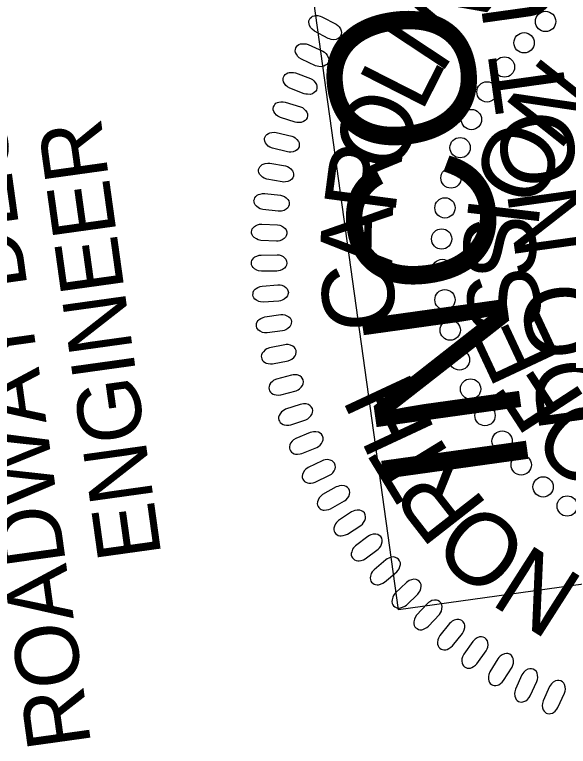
# Model space of a CAD drawing. Extents: x 477288 to 478604, y 497629 to 499448.
# Drawn here: x 477375.5 to 477419.1, y 499110 to 499167.6 of the extents above; entities that cross this region are included whole.
import ezdxf

# ---------------------------------------------------------------- set-up
doc = ezdxf.new("R2010")
doc.units = 0
for name, color, linetype in [('Sheet PE Seal Cell', 7, 'Continuous'), ('Sheet Plan CELL', 7, 'Continuous'), ('Sheet Sticker Incomplete CELL', 7, 'Continuous')]:
    doc.layers.add(name, color=color, linetype=linetype)

msp = doc.modelspace()

# ---------------------------------------------------------------- linework, layer by layer
at = {"layer": 'Sheet PE Seal Cell'}
for points in [[(477400.198, 499165.737), (477399.116, 499166.315), (477398.94, 499166.451), (477398.841, 499166.563), (477398.745, 499166.742), (477398.694, 499166.879), (477398.676, 499167.015), (477398.69, 499167.127), (477398.725, 499167.236), (477398.796, 499167.325), (477398.878, 499167.416), (477398.98, 499167.48), (477399.118, 499167.526), (477399.217, 499167.541), (477399.38, 499167.53), (477399.566, 499167.498), (477399.718, 499167.443), (477400.83, 499166.857), (477400.969, 499166.757), (477401.071, 499166.652), (477401.17, 499166.498), (477401.24, 499166.333), (477401.264, 499166.21), (477401.243, 499166.044), (477401.19, 499165.902), (477401.085, 499165.789), (477400.992, 499165.72), (477400.844, 499165.655), (477400.638, 499165.63), (477400.448, 499165.655), (477400.319, 499165.689)], [(477399.213, 499163.581), (477398.097, 499164.09), (477397.912, 499164.215), (477397.807, 499164.32), (477397.699, 499164.492), (477397.639, 499164.626), (477397.613, 499164.762), (477397.621, 499164.873), (477397.649, 499164.984), (477397.714, 499165.077), (477397.791, 499165.173), (477397.888, 499165.244), (477398.023, 499165.298), (477398.12, 499165.319), (477398.284, 499165.319), (477398.472, 499165.299), (477398.627, 499165.253), (477399.773, 499164.739), (477399.918, 499164.648), (477400.026, 499164.549), (477400.134, 499164.401), (477400.215, 499164.242), (477400.248, 499164.12), (477400.237, 499163.952), (477400.193, 499163.808), (477400.095, 499163.689), (477400.006, 499163.614), (477399.863, 499163.539), (477399.659, 499163.501), (477399.467, 499163.514), (477399.337, 499163.541)], [(477398.323, 499161.379), (477397.177, 499161.817), (477396.986, 499161.93), (477396.873, 499162.028), (477396.755, 499162.194), (477396.687, 499162.324), (477396.653, 499162.457), (477396.653, 499162.569), (477396.674, 499162.681), (477396.733, 499162.778), (477396.804, 499162.879), (477396.896, 499162.956), (477397.027, 499163.018), (477397.123, 499163.045), (477397.286, 499163.055), (477397.476, 499163.047), (477397.633, 499163.011), (477398.809, 499162.57), (477398.96, 499162.488), (477399.074, 499162.397), (477399.191, 499162.256), (477399.282, 499162.101), (477399.322, 499161.982), (477399.322, 499161.814), (477399.287, 499161.667), (477399.197, 499161.542), (477399.112, 499161.462), (477398.974, 499161.379), (477398.773, 499161.327), (477398.581, 499161.329), (477398.449, 499161.347)], [(477397.61, 499159.136), (477396.439, 499159.5), (477396.241, 499159.601), (477396.123, 499159.693), (477395.994, 499159.85), (477395.918, 499159.975), (477395.876, 499160.106), (477395.868, 499160.218), (477395.883, 499160.331), (477395.936, 499160.432), (477395.999, 499160.538), (477396.087, 499160.62), (477396.214, 499160.69), (477396.308, 499160.723), (477396.471, 499160.743), (477396.66, 499160.747), (477396.819, 499160.721), (477398.021, 499160.354), (477398.176, 499160.283), (477398.296, 499160.198), (477398.422, 499160.065), (477398.522, 499159.916), (477398.569, 499159.8), (477398.58, 499159.632), (477398.554, 499159.483), (477398.472, 499159.353), (477398.393, 499159.268), (477398.26, 499159.176), (477398.063, 499159.112), (477397.871, 499159.101), (477397.739, 499159.112)], [(477396.994, 499156.787), (477395.802, 499157.077), (477395.598, 499157.166), (477395.474, 499157.249), (477395.336, 499157.399), (477395.253, 499157.519), (477395.202, 499157.647), (477395.188, 499157.758), (477395.194, 499157.872), (477395.241, 499157.975), (477395.298, 499158.085), (477395.381, 499158.172), (477395.503, 499158.251), (477395.594, 499158.29), (477395.755, 499158.32), (477395.944, 499158.336), (477396.105, 499158.32), (477397.327, 499158.029), (477397.487, 499157.967), (477397.612, 499157.89), (477397.745, 499157.766), (477397.855, 499157.624), (477397.909, 499157.511), (477397.93, 499157.343), (477397.914, 499157.194), (477397.84, 499157.058), (477397.767, 499156.968), (477397.64, 499156.868), (477397.446, 499156.793), (477397.256, 499156.769), (477397.123, 499156.771)], [(477396.581, 499154.424), (477395.373, 499154.639), (477395.163, 499154.715), (477395.035, 499154.791), (477394.888, 499154.931), (477394.797, 499155.046), (477394.738, 499155.17), (477394.717, 499155.28), (477394.717, 499155.394), (477394.756, 499155.501), (477394.807, 499155.613), (477394.884, 499155.706), (477395.001, 499155.791), (477395.09, 499155.836), (477395.249, 499155.876), (477395.436, 499155.904), (477395.597, 499155.898), (477396.835, 499155.685), (477396.999, 499155.633), (477397.128, 499155.564), (477397.27, 499155.448), (477397.387, 499155.313), (477397.449, 499155.204), (477397.48, 499155.038), (477397.473, 499154.887), (477397.408, 499154.748), (477397.341, 499154.654), (477397.22, 499154.546), (477397.033, 499154.458), (477396.844, 499154.423), (477396.711, 499154.416)], [(477396.275, 499152.11), (477395.056, 499152.248), (477394.843, 499152.31), (477394.709, 499152.379), (477394.553, 499152.509), (477394.455, 499152.618), (477394.389, 499152.738), (477394.361, 499152.847), (477394.354, 499152.961), (477394.386, 499153.07), (477394.43, 499153.185), (477394.501, 499153.282), (477394.612, 499153.375), (477394.698, 499153.425), (477394.854, 499153.475), (477395.039, 499153.515), (477395.201, 499153.519), (477396.45, 499153.384), (477396.616, 499153.342), (477396.749, 499153.282), (477396.898, 499153.175), (477397.024, 499153.047), (477397.092, 499152.942), (477397.134, 499152.779), (477397.137, 499152.629), (477397.08, 499152.485), (477397.019, 499152.386), (477396.905, 499152.271), (477396.723, 499152.171), (477396.537, 499152.125), (477396.406, 499152.11)], [(477396.123, 499149.761), (477394.898, 499149.823), (477394.681, 499149.872), (477394.544, 499149.931), (477394.381, 499150.052), (477394.276, 499150.154), (477394.202, 499150.27), (477394.167, 499150.377), (477394.153, 499150.49), (477394.178, 499150.601), (477394.215, 499150.719), (477394.28, 499150.82), (477394.385, 499150.92), (477394.467, 499150.975), (477394.62, 499151.035), (477394.802, 499151.086), (477394.963, 499151.1), (477396.218, 499151.044), (477396.386, 499151.013), (477396.523, 499150.961), (477396.678, 499150.863), (477396.812, 499150.744), (477396.887, 499150.643), (477396.939, 499150.484), (477396.951, 499150.333), (477396.904, 499150.186), (477396.849, 499150.084), (477396.743, 499149.962), (477396.567, 499149.851), (477396.385, 499149.793), (477396.253, 499149.77)], [(477396.162, 499147.405), (477394.935, 499147.39), (477394.715, 499147.424), (477394.575, 499147.475), (477394.404, 499147.585), (477394.293, 499147.681), (477394.212, 499147.792), (477394.171, 499147.896), (477394.15, 499148.008), (477394.169, 499148.121), (477394.197, 499148.24), (477394.255, 499148.346), (477394.354, 499148.451), (477394.433, 499148.512), (477394.582, 499148.582), (477394.761, 499148.643), (477394.919, 499148.668), (477396.176, 499148.691), (477396.346, 499148.67), (477396.486, 499148.627), (477396.647, 499148.54), (477396.787, 499148.429), (477396.868, 499148.333), (477396.93, 499148.177), (477396.952, 499148.028), (477396.914, 499147.878), (477396.866, 499147.772), (477396.768, 499147.644), (477396.599, 499147.522), (477396.42, 499147.453), (477396.291, 499147.421)], [(477396.314, 499145.041), (477395.091, 499144.949), (477394.869, 499144.969), (477394.726, 499145.011), (477394.548, 499145.11), (477394.432, 499145.199), (477394.344, 499145.305), (477394.297, 499145.406), (477394.268, 499145.517), (477394.28, 499145.63), (477394.3, 499145.751), (477394.352, 499145.86), (477394.443, 499145.972), (477394.519, 499146.037), (477394.663, 499146.116), (477394.837, 499146.189), (477394.994, 499146.224), (477396.248, 499146.325), (477396.418, 499146.316), (477396.561, 499146.281), (477396.726, 499146.204), (477396.874, 499146.103), (477396.961, 499146.012), (477397.033, 499145.859), (477397.064, 499145.712), (477397.035, 499145.56), (477396.993, 499145.452), (477396.903, 499145.317), (477396.743, 499145.186), (477396.569, 499145.105), (477396.442, 499145.066)], [(477396.613, 499142.7), (477395.398, 499142.532), (477395.176, 499142.539), (477395.029, 499142.572), (477394.847, 499142.659), (477394.724, 499142.74), (477394.63, 499142.84), (477394.576, 499142.938), (477394.541, 499143.047), (477394.545, 499143.161), (477394.558, 499143.283), (477394.603, 499143.395), (477394.688, 499143.512), (477394.759, 499143.583), (477394.898, 499143.67), (477395.067, 499143.754), (477395.222, 499143.798), (477396.466, 499143.978), (477396.637, 499143.98), (477396.781, 499143.954), (477396.951, 499143.887), (477397.106, 499143.795), (477397.198, 499143.71), (477397.279, 499143.562), (477397.319, 499143.418), (477397.3, 499143.264), (477397.265, 499143.154), (477397.184, 499143.013), (477397.032, 499142.872), (477396.864, 499142.781), (477396.739, 499142.733)], [(477396.776, 499141.597), (477395.573, 499141.352), (477395.366, 499141.272), (477395.24, 499141.193), (477395.096, 499141.049), (477395.008, 499140.932), (477394.952, 499140.806), (477394.934, 499140.696), (477394.937, 499140.582), (477394.979, 499140.476), (477395.032, 499140.365), (477395.111, 499140.274), (477395.23, 499140.192), (477395.32, 499140.149), (477395.48, 499140.113), (477395.668, 499140.09), (477395.828, 499140.1), (477397.061, 499140.343), (477397.223, 499140.399), (477397.351, 499140.471), (477397.489, 499140.59), (477397.604, 499140.729), (477397.663, 499140.839), (477397.69, 499141.005), (477397.68, 499141.156), (477397.611, 499141.294), (477397.541, 499141.387), (477397.418, 499141.491), (477397.228, 499141.575), (477397.038, 499141.605), (477396.905, 499141.609)], [(477397.312, 499139.21), (477396.128, 499138.89), (477395.926, 499138.797), (477395.805, 499138.71), (477395.67, 499138.558), (477395.59, 499138.435), (477395.542, 499138.307), (477395.531, 499138.195), (477395.541, 499138.081), (477395.589, 499137.978), (477395.649, 499137.871), (477395.734, 499137.785), (477395.858, 499137.71), (477395.95, 499137.673), (477396.112, 499137.647), (477396.301, 499137.636), (477396.461, 499137.656), (477397.676, 499137.977), (477397.834, 499138.042), (477397.957, 499138.122), (477398.088, 499138.25), (477398.193, 499138.395), (477398.245, 499138.509), (477398.262, 499138.677), (477398.243, 499138.826), (477398.165, 499138.96), (477398.089, 499139.048), (477397.96, 499139.145), (477397.766, 499139.216), (477397.575, 499139.234), (477397.442, 499139.229)], [(477398.005, 499136.902), (477396.844, 499136.509), (477396.648, 499136.403), (477396.532, 499136.309), (477396.407, 499136.148), (477396.335, 499136.021), (477396.295, 499135.89), (477396.291, 499135.778), (477396.308, 499135.665), (477396.363, 499135.565), (477396.429, 499135.462), (477396.519, 499135.381), (477396.648, 499135.314), (477396.743, 499135.283), (477396.906, 499135.268), (477397.095, 499135.268), (477397.253, 499135.298), (477398.446, 499135.694), (477398.599, 499135.77), (477398.717, 499135.857), (477398.84, 499135.993), (477398.936, 499136.144), (477398.98, 499136.262), (477398.986, 499136.43), (477398.957, 499136.577), (477398.872, 499136.707), (477398.791, 499136.79), (477398.656, 499136.878), (477398.457, 499136.937), (477398.265, 499136.943), (477398.133, 499136.929)], [(477398.791, 499134.684), (477397.656, 499134.219), (477397.467, 499134.101), (477397.357, 499133.999), (477397.243, 499133.831), (477397.179, 499133.7), (477397.147, 499133.566), (477397.15, 499133.453), (477397.174, 499133.342), (477397.235, 499133.246), (477397.308, 499133.147), (477397.403, 499133.073), (477397.535, 499133.014), (477397.632, 499132.989), (477397.796, 499132.983), (477397.984, 499132.996), (477398.141, 499133.036), (477399.306, 499133.506), (477399.454, 499133.591), (477399.566, 499133.686), (477399.68, 499133.829), (477399.767, 499133.986), (477399.803, 499134.106), (477399.8, 499134.274), (477399.761, 499134.42), (477399.668, 499134.543), (477399.582, 499134.621), (477399.441, 499134.7), (477399.239, 499134.747), (477399.047, 499134.741), (477398.917, 499134.72)], [(477399.727, 499132.458), (477398.624, 499131.922), (477398.443, 499131.793), (477398.34, 499131.685), (477398.236, 499131.51), (477398.18, 499131.375), (477398.157, 499131.239), (477398.167, 499131.127), (477398.198, 499131.018), (477398.265, 499130.925), (477398.344, 499130.832), (477398.443, 499130.763), (477398.579, 499130.712), (477398.677, 499130.694), (477398.841, 499130.698), (477399.029, 499130.723), (477399.182, 499130.773), (477400.316, 499131.315), (477400.458, 499131.409), (477400.564, 499131.511), (477400.669, 499131.661), (477400.745, 499131.823), (477400.774, 499131.945), (477400.76, 499132.113), (477400.712, 499132.255), (477400.611, 499132.373), (477400.52, 499132.445), (477400.375, 499132.516), (477400.17, 499132.549), (477399.98, 499132.531), (477399.85, 499132.502)], [(477400.839, 499130.391), (477399.771, 499129.787), (477399.599, 499129.646), (477399.503, 499129.532), (477399.41, 499129.351), (477399.363, 499129.212), (477399.349, 499129.076), (477399.366, 499128.965), (477399.404, 499128.858), (477399.476, 499128.77), (477399.561, 499128.68), (477399.665, 499128.619), (477399.803, 499128.576), (477399.902, 499128.564), (477400.065, 499128.579), (477400.251, 499128.616), (477400.401, 499128.674), (477401.498, 499129.287), (477401.634, 499129.39), (477401.734, 499129.498), (477401.829, 499129.654), (477401.895, 499129.82), (477401.917, 499129.944), (477401.892, 499130.111), (477401.835, 499130.251), (477401.726, 499130.361), (477401.632, 499130.427), (477401.482, 499130.489), (477401.276, 499130.51), (477401.086, 499130.48), (477400.959, 499130.442)], [(477402.055, 499128.422), (477401.027, 499127.753), (477400.864, 499127.601), (477400.775, 499127.481), (477400.694, 499127.295), (477400.656, 499127.153), (477400.65, 499127.016), (477400.674, 499126.906), (477400.718, 499126.802), (477400.796, 499126.719), (477400.887, 499126.635), (477400.994, 499126.58), (477401.135, 499126.546), (477401.234, 499126.54), (477401.396, 499126.565), (477401.579, 499126.613), (477401.725, 499126.682), (477402.781, 499127.362), (477402.912, 499127.473), (477403.004, 499127.587), (477403.088, 499127.749), (477403.145, 499127.92), (477403.158, 499128.044), (477403.122, 499128.209), (477403.058, 499128.345), (477402.942, 499128.448), (477402.844, 499128.509), (477402.691, 499128.561), (477402.484, 499128.568), (477402.296, 499128.527), (477402.171, 499128.481)], [(477403.346, 499126.499), (477402.363, 499125.766), (477402.209, 499125.604), (477402.128, 499125.48), (477402.059, 499125.288), (477402.029, 499125.145), (477402.032, 499125.007), (477402.063, 499124.9), (477402.114, 499124.797), (477402.197, 499124.72), (477402.292, 499124.641), (477402.403, 499124.593), (477402.546, 499124.569), (477402.645, 499124.569), (477402.805, 499124.604), (477402.985, 499124.664), (477403.126, 499124.741), (477404.138, 499125.486), (477404.261, 499125.605), (477404.346, 499125.725), (477404.42, 499125.892), (477404.465, 499126.066), (477404.471, 499126.191), (477404.425, 499126.353), (477404.352, 499126.484), (477404.231, 499126.58), (477404.128, 499126.635), (477403.972, 499126.677), (477403.765, 499126.671), (477403.581, 499126.618), (477403.459, 499126.564)], [(477404.755, 499124.658), (477403.82, 499123.865), (477403.676, 499123.694), (477403.604, 499123.564), (477403.546, 499123.369), (477403.526, 499123.224), (477403.538, 499123.087), (477403.575, 499122.981), (477403.633, 499122.883), (477403.72, 499122.81), (477403.82, 499122.739), (477403.933, 499122.697), (477404.077, 499122.682), (477404.177, 499122.688), (477404.335, 499122.733), (477404.51, 499122.804), (477404.647, 499122.89), (477405.61, 499123.697), (477405.725, 499123.824), (477405.802, 499123.949), (477405.865, 499124.12), (477405.899, 499124.296), (477405.898, 499124.421), (477405.842, 499124.58), (477405.76, 499124.707), (477405.633, 499124.795), (477405.527, 499124.843), (477405.369, 499124.876), (477405.162, 499124.856), (477404.982, 499124.791), (477404.864, 499124.731)], [(477406.373, 499122.864), (477405.489, 499122.013), (477405.357, 499121.834), (477405.292, 499121.699), (477405.248, 499121.501), (477405.236, 499121.355), (477405.257, 499121.219), (477405.3, 499121.115), (477405.364, 499121.021), (477405.456, 499120.954), (477405.56, 499120.889), (477405.676, 499120.855), (477405.821, 499120.848), (477405.919, 499120.86), (477406.074, 499120.916), (477406.245, 499120.997), (477406.375, 499121.092), (477407.286, 499121.958), (477407.392, 499122.092), (477407.462, 499122.221), (477407.515, 499122.396), (477407.538, 499122.573), (477407.528, 499122.699), (477407.462, 499122.853), (477407.373, 499122.975), (477407.24, 499123.055), (477407.132, 499123.096), (477406.972, 499123.119), (477406.767, 499123.087), (477406.59, 499123.011), (477406.476, 499122.942)], [(477408.008, 499121.192), (477407.179, 499120.288), (477407.059, 499120.101), (477407.002, 499119.963), (477406.971, 499119.762), (477406.968, 499119.616), (477406.997, 499119.481), (477407.047, 499119.381), (477407.117, 499119.29), (477407.213, 499119.229), (477407.321, 499119.171), (477407.439, 499119.143), (477407.584, 499119.147), (477407.681, 499119.165), (477407.832, 499119.23), (477407.997, 499119.321), (477408.122, 499119.425), (477408.976, 499120.345), (477409.074, 499120.486), (477409.135, 499120.619), (477409.177, 499120.797), (477409.188, 499120.976), (477409.171, 499121.101), (477409.095, 499121.251), (477408.998, 499121.366), (477408.861, 499121.438), (477408.751, 499121.472), (477408.59, 499121.484), (477408.387, 499121.44), (477408.216, 499121.353), (477408.106, 499121.278)], [(477409.779, 499119.634), (477409.008, 499118.679), (477408.899, 499118.485), (477408.852, 499118.343), (477408.833, 499118.141), (477408.84, 499117.995), (477408.877, 499117.862), (477408.933, 499117.765), (477409.008, 499117.679), (477409.108, 499117.625), (477409.22, 499117.573), (477409.339, 499117.553), (477409.483, 499117.566), (477409.58, 499117.59), (477409.726, 499117.664), (477409.885, 499117.766), (477410.002, 499117.876), (477410.798, 499118.85), (477410.887, 499118.996), (477410.939, 499119.132), (477410.97, 499119.313), (477410.97, 499119.493), (477410.945, 499119.616), (477410.86, 499119.761), (477410.756, 499119.87), (477410.615, 499119.932), (477410.502, 499119.96), (477410.341, 499119.962), (477410.141, 499119.905), (477409.976, 499119.807), (477409.871, 499119.726)], [(477411.601, 499118.209), (477410.893, 499117.208), (477410.797, 499117.007), (477410.758, 499116.863), (477410.752, 499116.66), (477410.768, 499116.514), (477410.813, 499116.384), (477410.876, 499116.292), (477410.956, 499116.21), (477411.058, 499116.162), (477411.174, 499116.117), (477411.293, 499116.105), (477411.437, 499116.126), (477411.531, 499116.157), (477411.673, 499116.24), (477411.825, 499116.352), (477411.936, 499116.469), (477412.668, 499117.491), (477412.748, 499117.642), (477412.792, 499117.782), (477412.811, 499117.964), (477412.8, 499118.142), (477412.767, 499118.264), (477412.673, 499118.404), (477412.563, 499118.506), (477412.418, 499118.56), (477412.304, 499118.58), (477412.142, 499118.572), (477411.946, 499118.502), (477411.788, 499118.395), (477411.689, 499118.306)], [(477413.594, 499116.857), (477412.949, 499115.814), (477412.866, 499115.607), (477412.837, 499115.461), (477412.843, 499115.258), (477412.868, 499115.114), (477412.922, 499114.987), (477412.99, 499114.899), (477413.075, 499114.822), (477413.18, 499114.78), (477413.298, 499114.743), (477413.418, 499114.738), (477413.56, 499114.769), (477413.653, 499114.805), (477413.788, 499114.897), (477413.934, 499115.019), (477414.037, 499115.142), (477414.703, 499116.207), (477414.774, 499116.364), (477414.808, 499116.506), (477414.816, 499116.689), (477414.794, 499116.866), (477414.753, 499116.986), (477414.651, 499117.119), (477414.535, 499117.214), (477414.386, 499117.259), (477414.271, 499117.271), (477414.11, 499117.254), (477413.92, 499117.172), (477413.768, 499117.055), (477413.675, 499116.96)], [(477415.49, 499115.582), (477414.972, 499114.47), (477414.914, 499114.255), (477414.902, 499114.107), (477414.932, 499113.905), (477414.974, 499113.765), (477415.042, 499113.646), (477415.12, 499113.566), (477415.214, 499113.5), (477415.324, 499113.471), (477415.445, 499113.448), (477415.565, 499113.457), (477415.702, 499113.504), (477415.79, 499113.551), (477415.914, 499113.658), (477416.044, 499113.796), (477416.131, 499113.931), (477416.668, 499115.067), (477416.72, 499115.23), (477416.737, 499115.376), (477416.723, 499115.558), (477416.681, 499115.732), (477416.626, 499115.845), (477416.509, 499115.966), (477416.382, 499116.047), (477416.23, 499116.074), (477416.114, 499116.073), (477415.956, 499116.036), (477415.777, 499115.933), (477415.64, 499115.799), (477415.558, 499115.693)], [(477417.661, 499114.658), (477417.152, 499113.542), (477417.095, 499113.327), (477417.084, 499113.178), (477417.116, 499112.977), (477417.159, 499112.837), (477417.228, 499112.718), (477417.307, 499112.639), (477417.401, 499112.574), (477417.511, 499112.545), (477417.632, 499112.523), (477417.752, 499112.534), (477417.889, 499112.581), (477417.977, 499112.629), (477418.1, 499112.738), (477418.229, 499112.876), (477418.315, 499113.012), (477418.843, 499114.153), (477418.893, 499114.316), (477418.91, 499114.462), (477418.894, 499114.644), (477418.85, 499114.818), (477418.795, 499114.931), (477418.677, 499115.05), (477418.549, 499115.13), (477418.397, 499115.156), (477418.281, 499115.154), (477418.123, 499115.116), (477417.945, 499115.011), (477417.809, 499114.876), (477417.728, 499114.77)]]:
    msp.add_lwpolyline(points, close=True, dxfattribs=at)
for centre in [(477417.351, 499167.068), (477415.654, 499165.386), (477414.109, 499163.483), (477412.732, 499161.523), (477411.506, 499159.343), (477410.607, 499157.128), (477409.893, 499154.738), (477409.416, 499152.381), (477409.153, 499149.932), (477409.205, 499147.528), (477409.415, 499145.145), (477409.828, 499142.751), (477410.556, 499140.4), (477411.437, 499138.111), (477412.573, 499136.017), (477413.923, 499134.01), (477415.431, 499132.129), (477417.159, 499130.399), (477419.057, 499128.894)]:
    msp.add_circle(centre, 0.801, dxfattribs=at)
at = {"layer": 'Sheet Sticker Incomplete CELL'}
msp.add_lwpolyline([(477429.019, 499123.954), (477405.744, 499120.714), (477385.482, 499266.311), (477408.757, 499269.55)], close=True, dxfattribs=at)

# ---------------------------------------------------------------- texts
at = {"layer": 'Sheet PE Seal Cell'}
for s, rotation, p in [('N', 50.08486, (477410.173, 499164.722)), ('I', 56.57422, (477409.016, 499162.739)), ('N', 51.57293, (477418.39, 499156.746)), ('L', 63.06358, (477407.551, 499159.816)), ('O', 69.55293, (477405.697, 499154.78)), ('O', 67.45252, (477416.702, 499152.158)), ('R', 82.53164, (477405.456, 499151.763)), ('A', 89.021, (477405.25, 499147.487)), ('I', 83.33212, (477416.739, 499150.645)), ('S', 91.27191, (477416.637, 499146.794)), ('C', 95.51036, (477405.674, 499142.926)), ('S', 99.21171, (477417.27, 499142.984)), ('E', 115.09131, (477418.601, 499140.375)), ('F', 123.0311, (477420.592, 499137.229)), ('H', 114.97843, (477408.712, 499134.762)), ('O', 138.9107, (477424.211, 499134)), ('T', 121.46778, (477410.546, 499131.808)), ('R', 127.95714, (477412.891, 499128.882)), ('O', 140.93586, (477416.369, 499125.857)), ('N', 147.42521, (477420.55, 499123.06))]:
    msp.add_text(s, height=5.669, rotation=rotation, dxfattribs=at).set_placement(p)
at = {"layer": 'Sheet Plan CELL'}
for s, p in [('ROADWAY DESIGN', (477381.525, 499110.1)), ('ENGINEER', (477387.063, 499124.993))]:
    msp.add_text(s, height=5.0001, rotation=97.92268, dxfattribs=at).set_placement(p)
at = {"layer": 'Sheet Sticker Incomplete CELL'}
for s, height, p in [('INCOMPLETE PLANS', 11.52, (477416.197, 499131.205)), ('DO NOT USE FOR R/W ACQUISITION', 5.76, (477422.633, 499135.382))]:
    msp.add_text(s, height=height, rotation=97.92268, dxfattribs=at).set_placement(p)

doc.saveas('drawing.dxf')
